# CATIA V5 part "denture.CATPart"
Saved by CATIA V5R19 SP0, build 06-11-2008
Part number: denturepetite
Bounding box of the stored display mesh (mm): x -9 to 15, y 0 to 80, z -10 to 80
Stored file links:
  G:\EU_thinkMotion\CFAO_2010\SIL_groupe2\SIL_groupe2\A reprendre\vfouquet\fouquet\denture.CATPart
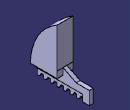
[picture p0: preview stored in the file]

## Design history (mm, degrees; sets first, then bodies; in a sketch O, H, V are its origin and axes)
Body1 (main body)
  Sketch1 on yz-plane, origin (0, 0, 0), H (0, 1, 0), V (0, 0, 1)
    line L1 (0, -10) -> (3, -10)
    line L2 (3, -10) -> (6, -5)
    line L3 (10, 0) -> (0, 0)
    line L4 (0, 0) -> (0, -10)
    line L5 (6, -5) -> (10, -5)
    line L6 (10, -5) -> (10, 0)
    length L4 = 10
    length L3 = 10
    length L1 = 3
    length L6 = 5
  Pad1: profile Sketch1, direction (1, 0, 0), length 5
  RectPattern1: of the body so far, direction 1 instances 7, spacing 10, along end face of Pad1
  Sketch2 on yz-plane, origin (0, 0, 0), H (0, 1, 0), V (0, 0, 1)
    line L1 (70, 0) -> (70, -10)
    line L2 (70, -10) -> (80, -10)
    line L3 (80, -10) -> (80, 10)
    line L4 (0, 10) -> (0, 0)
    line L5 (0, 0) -> (70, 0)
    line L6 (20, 10) -> (0, 10)
    line L7 (40, 10) -> (40, 20)
    line L8 (40, 20) -> (60, 10)
    line L9 (20, 10) -> (40, 10)
    line L10 (60, 10) -> (80, 10)
    length L2 = 10
    length L3 = 20
  Pad2: profile Sketch2, direction (1, 0, 0), length 6
  Sketch3 on yz-plane, origin (0, 0, 0), H (0, 1, 0), V (0, 0, 1)
    arc A1 centre (78.3333, 11.6667) radius 78.3511 from (0, 10) to (40, 80) cw
    line L1 (40, 80) -> (40, 20)
    line L2 (40, 10) -> (0, 10)
    line L3 (40, 20) -> (40, 10)
    length L2 = 40
    radius A1 = 78.3511
  Pad3: profile Sketch3, direction (1, 0, 0), length 15, opposite side length 9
